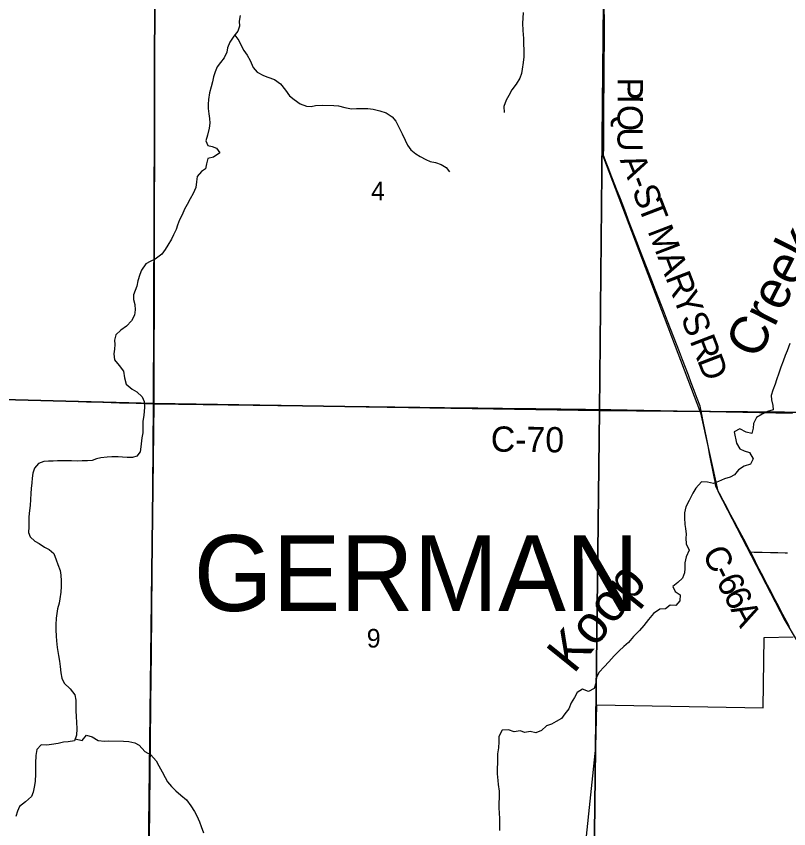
# Model space of a CAD drawing. Extents: x -11.1 to 34, y -3.9 to 22.
# Drawn here: x 3.076 to 4.812, y 16.345 to 18.172 of the extents above; entities that cross this region are included whole.
import ezdxf

# ---------------------------------------------------------------- set-up
doc = ezdxf.new("R2010")
doc.units = 0
for name, color, linetype in [('GM_X_Corporation', 7, 'Continuous'), ('GM_X_County_Road', 7, 'Continuous'), ('GM_X_County_Road_Text', 7, 'Continuous'), ('GM_X_Minor_River', 7, 'Continuous'), ('GM_X_Minor_River_Text', 7, 'Continuous'), ('GM_X_Rail_Line', 7, 'Continuous'), ('GM_X_Section_Text', 7, 'Continuous'), ('GM_X_Township_Road', 7, 'Continuous'), ('GM_X_Township_Text', 7, 'Continuous')]:
    doc.layers.add(name, color=color, linetype=linetype)

msp = doc.modelspace()

# ---------------------------------------------------------------- linework, layer by layer
at = {"layer": 'GM_X_Corporation'}
for points in [[(2.3861, 18.3151), (3.3764, 18.2972), (3.3877, 18.2966), (3.3852, 17.301), (2.3686, 17.3282)], [(4.3765, 18.281), (4.3966, 18.2798), (4.3866, 17.2855), (3.3852, 17.301), (3.3877, 18.2966)], [(5.3892, 18.2641), (5.385, 17.2762), (4.3866, 17.2855), (4.3966, 18.2798)], [(3.3852, 17.301), (3.3734, 16.2901), (2.3594, 16.3176), (2.3686, 17.3282)], [(3.3852, 17.301), (4.3866, 17.2855), (4.3746, 16.2728), (3.3734, 16.2901)], [(5.385, 17.2762), (5.3715, 16.2638), (4.3746, 16.2728), (4.3866, 17.2855)]]:
    msp.add_lwpolyline(points, close=True, dxfattribs=at)
msp.add_lwpolyline([(4.8741, 15.7548), (4.7379, 15.7575), (4.4726, 15.7622), (4.3481, 15.7643), (4.3561, 16.2709), (4.3703, 16.2707), (4.3702, 16.3146), (4.356, 16.3148), (4.3787, 16.5288), (4.3805, 16.6238), (4.7548, 16.6175), (4.7564, 16.7751), (4.8221, 16.7767)], dxfattribs=at)
at = {"layer": 'GM_X_County_Road'}
for points in [[(4.6463, 17.1259), (4.6449, 17.133), (4.6413, 17.1513), (4.6378, 17.1696), (4.6342, 17.1879), (4.6306, 17.2062), (4.627, 17.2245), (4.6235, 17.2428), (4.6199, 17.2611), (4.6177, 17.2724), (4.6155, 17.2836), (4.6132, 17.2953), (4.6065, 17.3127), (4.5998, 17.3301), (4.5931, 17.3475), (4.5864, 17.3649), (4.5797, 17.3823), (4.573, 17.3996), (4.5663, 17.417), (4.5596, 17.4344), (4.5529, 17.4518), (4.5462, 17.4692), (4.5394, 17.4866), (4.5327, 17.504), (4.526, 17.5214), (4.5193, 17.5388), (4.5126, 17.5562), (4.5059, 17.5736), (4.4992, 17.591), (4.4925, 17.6084), (4.4858, 17.6257), (4.4791, 17.6431), (4.4724, 17.6605), (4.4657, 17.6779), (4.459, 17.6953), (4.4523, 17.7127), (4.4456, 17.7301), (4.4389, 17.7475), (4.4322, 17.7649), (4.4268, 17.7788), (4.4215, 17.7927), (4.4148, 17.8101), (4.4081, 17.8275), (4.4021, 17.8432), (4.3961, 17.8588), (4.3962, 17.8775), (4.3963, 17.8961), (4.3964, 17.9147), (4.3966, 17.9334), (4.3967, 17.952), (4.3968, 17.9707), (4.3969, 17.9893), (4.3971, 18.0079), (4.3972, 18.0266), (4.3973, 18.0452), (4.3974, 18.0639), (4.3976, 18.0825), (4.3977, 18.1011), (4.3978, 18.1198), (4.3979, 18.1384), (4.398, 18.1571), (4.3982, 18.1757)], [(3.0663, 17.3101), (3.0849, 17.3096), (3.1035, 17.309), (3.1222, 17.3085), (3.1408, 17.3079), (3.1595, 17.3074), (3.1781, 17.3069), (3.1967, 17.3063), (3.2154, 17.3058), (3.234, 17.3052), (3.2526, 17.3047), (3.2713, 17.3041), (3.2899, 17.3036), (3.3085, 17.303), (3.3272, 17.3025), (3.3458, 17.302), (3.3644, 17.3014), (3.3747, 17.3011), (3.3849, 17.3008), (3.4035, 17.3006), (3.4222, 17.3003), (3.4408, 17.3), (3.4595, 17.2998), (3.4781, 17.2995), (3.4967, 17.2993), (3.5154, 17.299), (3.534, 17.2988), (3.5527, 17.2985), (3.5713, 17.2982), (3.59, 17.298), (3.6086, 17.2977), (3.6272, 17.2975), (3.6459, 17.2972), (3.6645, 17.297), (3.6832, 17.2967), (3.7018, 17.2964), (3.7204, 17.2962), (3.7391, 17.2959), (3.7577, 17.2957), (3.7764, 17.2954), (3.795, 17.2952), (3.8136, 17.2949), (3.8323, 17.2946), (3.8509, 17.2944), (3.8696, 17.2941), (3.8796, 17.294), (3.8896, 17.2938), (3.9083, 17.2936), (3.9269, 17.2934), (3.9455, 17.2932), (3.9642, 17.2929), (3.9828, 17.2927), (4.0015, 17.2925), (4.0201, 17.2923), (4.0388, 17.2921), (4.0574, 17.2918), (4.076, 17.2916), (4.0947, 17.2914), (4.1133, 17.2912), (4.132, 17.2909), (4.1506, 17.2907), (4.1692, 17.2905), (4.1879, 17.2903), (4.2065, 17.29), (4.2252, 17.2898), (4.2438, 17.2896), (4.2624, 17.2894), (4.2811, 17.2891), (4.2997, 17.2889), (4.3184, 17.2887), (4.337, 17.2885), (4.3557, 17.2882), (4.3743, 17.288), (4.3838, 17.2879), (4.3933, 17.2878), (4.4119, 17.2874), (4.4305, 17.2871), (4.4492, 17.2867), (4.4678, 17.2864), (4.4864, 17.286), (4.5051, 17.2857), (4.5237, 17.2853), (4.5423, 17.285), (4.561, 17.2846), (4.5796, 17.2843), (4.5975, 17.284), (4.6155, 17.2836)], [(4.6155, 17.2836), (4.6341, 17.2833), (4.6527, 17.2829), (4.6714, 17.2826), (4.69, 17.2822), (4.7087, 17.2819), (4.7273, 17.2815), (4.7459, 17.2812), (4.7616, 17.2809)], [(4.7616, 17.2809), (4.7646, 17.2808), (4.7832, 17.2805), (4.8018, 17.2802), (4.8205, 17.2798)], [(4.8133, 16.7992), (4.8076, 16.8104), (4.799, 16.827), (4.7904, 16.8435), (4.7818, 16.86), (4.7732, 16.8765), (4.7645, 16.893), (4.7559, 16.9096), (4.7509, 16.9192), (4.7458, 16.9288), (4.7374, 16.9454), (4.7318, 16.9565), (4.7261, 16.9675), (4.724, 16.9717), (4.7152, 16.9881), (4.7064, 17.0046), (4.6976, 17.021), (4.6898, 17.0356), (4.6819, 17.0502), (4.6733, 17.0668), (4.6648, 17.0833), (4.6566, 17.099), (4.6485, 17.1148), (4.6463, 17.1259)]]:
    msp.add_lwpolyline(points, dxfattribs=at)
at = {"layer": 'GM_X_Minor_River'}
for points in [[(3.5792, 18.1736), (3.577, 18.1604), (3.5779, 18.1493), (3.5742, 18.138), (3.5653, 18.1268), (3.5562, 18.1133), (3.5514, 18.1005), (3.5493, 18.0907), (3.5433, 18.0783), (3.5355, 18.0679), (3.5277, 18.0578), (3.5232, 18.0465), (3.5196, 18.0352), (3.5174, 18.0242), (3.5141, 18.0129), (3.5108, 17.9997), (3.5086, 17.9841), (3.5076, 17.9743), (3.5077, 17.964), (3.5094, 17.9522), (3.5103, 17.9415), (3.5112, 17.9316), (3.5101, 17.9199), (3.506, 17.9044), (3.5027, 17.8916), (3.507, 17.8808), (3.5168, 17.8791), (3.5266, 17.8754), (3.5336, 17.8646), (3.5197, 17.8551), (3.5071, 17.8519), (3.5038, 17.8402), (3.502, 17.8289), (3.4924, 17.8226), (3.4827, 17.8115), (3.4816, 17.7993), (3.4798, 17.7864), (3.4742, 17.7733), (3.4675, 17.7613), (3.4608, 17.7485), (3.4545, 17.738), (3.4493, 17.7252)], [(4.2155, 18.1802), (4.2144, 18.1669), (4.2138, 18.1563)], [(4.2138, 18.1563), (4.2142, 18.1392), (4.2157, 18.1217), (4.2162, 18.1103), (4.217, 18.0947), (4.2167, 18.0806), (4.2156, 18.0674), (4.2134, 18.0526), (4.2113, 18.0428), (4.2076, 18.0326), (4.1993, 18.0191), (4.1896, 18.0061), (4.1828, 17.9933), (4.1769, 17.9828), (4.172, 17.9688), (4.1725, 17.9555)], [(3.5672, 18.1292), (3.5764, 18.1171), (3.5807, 18.1071), (3.588, 18.0944), (3.595, 18.0843), (3.6023, 18.0724), (3.6084, 18.0567), (3.6177, 18.0462), (3.6319, 18.0383), (3.6417, 18.035), (3.6564, 18.0294), (3.6698, 18.0196), (3.6812, 18.0052), (3.6904, 17.9929), (3.7009, 17.9847), (3.7143, 17.9745), (3.7286, 17.9692), (3.7388, 17.969), (3.7484, 17.9706), (3.7636, 17.9718), (3.7897, 17.9712), (3.8007, 17.9702), (3.815, 17.9664), (3.8298, 17.9638), (3.8408, 17.9643), (3.8506, 17.9645), (3.8662, 17.9641), (3.8783, 17.9627), (3.893, 17.9593), (3.9077, 17.9544), (3.9212, 17.9458), (3.9289, 17.9357), (3.9369, 17.9207), (3.9434, 17.9073), (3.9499, 17.8931), (3.9558, 17.8819), (3.9631, 17.8715), (3.9743, 17.8625), (3.984, 17.8566), (3.9964, 17.8494), (4.0061, 17.8454), (4.0182, 17.8425), (4.0314, 17.8384), (4.0426, 17.8316), (4.05, 17.8216)], [(3.4493, 17.7252), (3.4433, 17.7139), (3.4385, 17.7023), (3.4356, 17.6921), (3.4297, 17.6804), (3.4249, 17.6703), (3.417, 17.6568), (3.4111, 17.647), (3.4037, 17.6369), (3.3886, 17.6255), (3.3775, 17.6204), (3.3675, 17.615), (3.3577, 17.6008), (3.3541, 17.591), (3.35, 17.577), (3.3471, 17.5649), (3.3434, 17.5551), (3.3402, 17.5453), (3.3399, 17.5346), (3.3427, 17.5239), (3.344, 17.5114), (3.3422, 17.5), (3.3351, 17.4869), (3.3242, 17.4753), (3.3118, 17.4661), (3.2999, 17.4557), (3.2969, 17.4436), (3.2978, 17.4337), (3.2972, 17.4235), (3.2955, 17.4125), (3.2971, 17.3996), (3.3074, 17.3864), (3.3174, 17.3736), (3.3197, 17.3587), (3.3236, 17.345), (3.3366, 17.3336), (3.3471, 17.3277), (3.3593, 17.316), (3.364, 17.3056), (3.3649, 17.2923), (3.363, 17.2753), (3.3611, 17.2609), (3.3606, 17.2354), (3.3588, 17.224), (3.3561, 17.2036), (3.3547, 17.1926), (3.3476, 17.1828), (3.3373, 17.1797), (3.3256, 17.1799), (3.3154, 17.1805), (3.3055, 17.1811), (3.2911, 17.1815), (3.2805, 17.1806), (3.2668, 17.1794), (3.2565, 17.1769), (3.2469, 17.1734), (3.2367, 17.1721), (3.2245, 17.172), (3.2131, 17.1718), (3.2003, 17.1725), (3.1904, 17.1727), (3.1794, 17.1726), (3.1688, 17.1721), (3.1593, 17.1719), (3.149, 17.1714), (3.1388, 17.1705), (3.1262, 17.1666), (3.1172, 17.1558), (3.1135, 17.1448), (3.1121, 17.1331), (3.1112, 17.1228), (3.1101, 17.1099), (3.1091, 17.0986), (3.1084, 17.0856), (3.1077, 17.0716), (3.1064, 17.0606), (3.1049, 17.0466), (3.1047, 17.0355), (3.1048, 17.0237), (3.1041, 17.0116), (3.1077, 17.0012), (3.1181, 16.9919), (3.1279, 16.9867), (3.1402, 16.9784), (3.1507, 16.9729), (3.1611, 16.9643), (3.1665, 16.9501), (3.1697, 16.9397), (3.1751, 16.9256), (3.1764, 16.9153), (3.1776, 16.9023), (3.1777, 16.8901), (3.1767, 16.8772), (3.1744, 16.8624), (3.1727, 16.8526), (3.1694, 16.8394), (3.168, 16.8291), (3.1663, 16.8189), (3.1652, 16.8041), (3.1653, 16.7923), (3.1661, 16.7782)], [(4.8144, 17.4357), (4.8083, 17.4195), (4.8043, 17.4094), (4.7995, 17.3962), (4.7942, 17.383), (4.7894, 17.3691), (4.7845, 17.3547), (4.7813, 17.3449)], [(4.7813, 17.3449), (4.7764, 17.3313), (4.7727, 17.3193), (4.7733, 17.3094), (4.776, 17.2968), (4.7766, 17.2872), (4.7643, 17.283), (4.7521, 17.2776), (4.7394, 17.2695), (4.733, 17.2559), (4.7324, 17.2461), (4.7291, 17.234), (4.7163, 17.2369), (4.702, 17.2445), (4.6893, 17.2376), (4.6949, 17.2123), (4.7018, 17.1996), (4.7115, 17.1949), (4.7236, 17.1912), (4.732, 17.1769), (4.7264, 17.1652), (4.7115, 17.1606), (4.6992, 17.1522), (4.6902, 17.141), (4.6806, 17.1359), (4.668, 17.1316), (4.6539, 17.1262), (4.6428, 17.1215), (4.6292, 17.1241), (4.6159, 17.1252), (4.6031, 17.1111), (4.5964, 17.0998), (4.5884, 17.0829), (4.5809, 17.069), (4.578, 17.0554), (4.5777, 17.0443), (4.5785, 17.0295), (4.5798, 17.02), (4.5818, 17.0077), (4.5809, 16.9983), (4.5817, 16.9857), (4.5886, 16.9715), (4.5815, 16.9564), (4.5785, 16.9432), (4.5782, 16.9302), (4.5776, 16.9207), (4.5732, 16.9087), (4.5628, 16.899), (4.5512, 16.8902), (4.5566, 16.879), (4.5678, 16.8708), (4.5675, 16.8575), (4.5582, 16.8474), (4.5457, 16.8477), (4.5353, 16.84), (4.522, 16.8387), (4.5081, 16.8292), (4.4972, 16.8157), (4.4867, 16.8019), (4.4766, 16.7911), (4.463, 16.7773), (4.4521, 16.7643), (4.4416, 16.7554), (4.4308, 16.745), (4.4199, 16.7338), (4.4075, 16.7208), (4.397, 16.7096), (4.3858, 16.6977), (4.3798, 16.686), (4.3788, 16.6728), (4.3751, 16.6603), (4.362, 16.6537), (4.3489, 16.6594), (4.3366, 16.652), (4.3303, 16.6404), (4.3232, 16.6284), (4.3176, 16.6148), (4.309, 16.6036), (4.3012, 16.5935), (4.2896, 16.5865), (4.2793, 16.5807), (4.2674, 16.5764), (4.2562, 16.5664), (4.2439, 16.561), (4.2307, 16.5643), (4.2193, 16.5615), (4.2087, 16.5652), (4.195, 16.5632), (4.1826, 16.5681), (4.1682, 16.5669), (4.1603, 16.5526), (4.1604, 16.5408), (4.1597, 16.5271), (4.1579, 16.5135), (4.1575, 16.4929), (4.1569, 16.4815), (4.157, 16.4686), (4.1582, 16.4541), (4.1595, 16.4446), (4.1614, 16.4297), (4.1615, 16.4152)], [(3.1661, 16.7782), (3.167, 16.7675), (3.1686, 16.753), (3.1716, 16.7347), (3.1736, 16.7221), (3.1749, 16.7103), (3.1768, 16.6962), (3.1789, 16.684), (3.1843, 16.6724), (3.1977, 16.6596), (3.208, 16.6464), (3.2104, 16.6342), (3.2105, 16.6205), (3.2106, 16.611), (3.2111, 16.5973), (3.2116, 16.5847), (3.2124, 16.5702), (3.2121, 16.5558), (3.2076, 16.5429), (3.1928, 16.5406), (3.1829, 16.5397), (3.1707, 16.5369), (3.1558, 16.5346), (3.1452, 16.5333), (3.1323, 16.534), (3.1226, 16.5232), (3.1204, 16.5099), (3.1196, 16.4925), (3.1198, 16.4818), (3.1195, 16.4681), (3.1188, 16.4525), (3.1174, 16.4423), (3.1144, 16.4275), (3.1104, 16.4177), (3.0976, 16.4062), (3.0838, 16.3955), (3.079, 16.385), (3.0757, 16.3733)], [(3.2091, 16.5473), (3.2247, 16.5437), (3.2344, 16.5556), (3.2473, 16.5519), (3.2604, 16.5436), (3.2751, 16.5425), (3.2846, 16.5427), (3.3172, 16.542), (3.3293, 16.5413), (3.3429, 16.5383), (3.3527, 16.5331), (3.3653, 16.5192), (3.3788, 16.5116), (3.391, 16.4984), (3.3968, 16.4872), (3.4041, 16.4734), (3.411, 16.4607), (3.4161, 16.451), (3.425, 16.4406), (3.435, 16.4308), (3.4462, 16.4207), (3.4589, 16.4101), (3.4688, 16.3966), (3.4773, 16.3842), (3.482, 16.3746), (3.4881, 16.3611), (3.4917, 16.3508), (3.4974, 16.3362)], [(4.1615, 16.4152), (4.1609, 16.4038), (4.161, 16.3913), (4.1615, 16.3817), (4.1623, 16.3669), (4.1624, 16.3524), (4.1625, 16.3414)]]:
    msp.add_lwpolyline(points, dxfattribs=at)
at = {"layer": 'GM_X_Rail_Line'}
msp.add_lwpolyline([(4.3976, 18.2496), (4.3933, 17.8598), (4.614, 17.2805), (4.6529, 17.1043), (4.8034, 16.8133), (4.8306, 16.7671), (4.8773, 16.7089)], dxfattribs=at)
at = {"layer": 'GM_X_Township_Road'}
for points in [[(3.3759, 16.3296), (3.3761, 16.3483), (3.3763, 16.3669), (3.3765, 16.3856), (3.3767, 16.4042), (3.3769, 16.4228), (3.3771, 16.4415), (3.3773, 16.4601), (3.3775, 16.4788), (3.3777, 16.4974), (3.3778, 16.516), (3.378, 16.5347), (3.3782, 16.5533), (3.3784, 16.572), (3.3786, 16.5906), (3.3788, 16.6093), (3.379, 16.6279), (3.3792, 16.6465), (3.3794, 16.6652), (3.3796, 16.6838), (3.3798, 16.7025), (3.38, 16.7211), (3.3802, 16.7397), (3.3804, 16.7584), (3.3806, 16.7767), (3.3808, 16.7951), (3.3809, 16.8137), (3.3811, 16.8324), (3.3812, 16.851), (3.3814, 16.8696), (3.3815, 16.8883), (3.3817, 16.9069), (3.3818, 16.9256), (3.382, 16.9442), (3.3821, 16.9628), (3.3823, 16.9815), (3.3824, 17.0001), (3.3826, 17.0188), (3.3827, 17.0374), (3.3829, 17.0561), (3.3831, 17.0747), (3.3832, 17.0933), (3.3834, 17.112), (3.3835, 17.1306), (3.3837, 17.1493), (3.3838, 17.1679), (3.384, 17.1865), (3.3841, 17.2052), (3.3843, 17.2238), (3.3844, 17.2425), (3.3846, 17.2611), (3.3847, 17.2797), (3.3848, 17.2903), (3.3849, 17.3008), (3.385, 17.3195), (3.3851, 17.3754), (3.3853, 17.4127), (3.3866, 17.8244), (3.3867, 17.8431), (3.3867, 17.8617), (3.3868, 17.8803), (3.3869, 17.899), (3.3869, 17.9176), (3.387, 17.9363), (3.3871, 17.9549), (3.3871, 17.9735), (3.3872, 17.9922), (3.3873, 18.0108), (3.3873, 18.0295), (3.3874, 18.0481), (3.3875, 18.0668), (3.3875, 18.0854), (3.3876, 18.104), (3.3877, 18.1227), (3.3878, 18.1413), (3.3878, 18.16), (3.3879, 18.1786)], [(4.7261, 16.9675), (4.734, 16.9673), (4.7526, 16.9669), (4.7712, 16.9665), (4.7876, 16.9661), (4.8039, 16.9657), (4.8088, 16.9656)]]:
    msp.add_lwpolyline(points, dxfattribs=at)

# ---------------------------------------------------------------- texts
at = {"layer": 'GM_X_County_Road_Text'}
for s, height, rotation, p in [('P', 0.0568, 269.7078, (4.4277, 18.0341)), ('I', 0.0568, 269.7073, (4.4275, 17.9958)), ('Q', 0.0568, 269.7137, (4.4274, 17.9724)), ('U', 0.0568, 270.1276, (4.4271, 17.922)), ('A', 0.0568, 292.183, (4.4318, 17.8487)), ('-', 0.0568, 290.9918, (4.4506, 17.8027)), ('S', 0.0568, 290.9979, (4.459, 17.7809)), ('T', 0.0568, 290.9944, (4.4727, 17.7451)), ('M', 0.0568, 290.9954, (4.4942, 17.6891)), ('A', 0.0568, 290.995, (4.5163, 17.6315)), ('R', 0.0568, 290.996, (4.5342, 17.5848)), ('Y', 0.0568, 290.9971, (4.5509, 17.5413)), ('S', 0.0568, 290.9954, (4.5689, 17.4946)), ('R', 0.0568, 290.996, (4.5889, 17.4425)), ('D', 0.0568, 290.9954, (4.6056, 17.3989)), ('C-70', 0.05682, 359.3142, (4.1423, 17.1931)), ('C', 0.0568, 296.8243, (4.6164, 16.9645)), ('-', 0.0568, 296.843, (4.6375, 16.9229)), ('6', 0.0568, 296.8981, (4.648, 16.902)), ('6', 0.0568, 297.087, (4.6639, 16.8706)), ('A', 0.0568, 297.8395, (4.6803, 16.8387))]:
    msp.add_text(s, height=height, rotation=rotation, dxfattribs=at).set_placement(p)
at = {"layer": 'GM_X_Minor_River_Text'}
for s, rotation, p in [('Creek', 63.05, (4.7422, 17.3976)), ('Koop', 51.0974, (4.3288, 16.6917))]:
    msp.add_text(s, height=0.08523, rotation=rotation, dxfattribs=at).set_placement(p)
at = {"layer": 'GM_X_Section_Text'}
for s, p in [('4', (3.8735, 17.758)), ('9', (3.8639, 16.7527))]:
    msp.add_text(s, height=0.0419, rotation=0, dxfattribs=at).set_placement(p)
at = {"layer": 'GM_X_Township_Text'}
msp.add_text('GERMAN', height=0.17045, rotation=0, dxfattribs=at).set_placement((3.4753, 16.8348))

doc.saveas('drawing.dxf')
